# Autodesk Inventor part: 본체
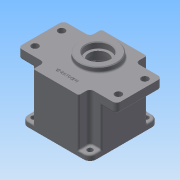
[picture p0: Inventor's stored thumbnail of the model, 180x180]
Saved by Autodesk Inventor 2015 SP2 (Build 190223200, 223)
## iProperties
Created: 2015-06
Part Number: 본체
Material: 일반
Document SubType Name: Modeling
Designer: AMC
Density: 1 g/cm^3
Appearance: 기본값
Author: AMC
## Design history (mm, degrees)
sketch "스케치1"
  geometry: L1 (65, 30)-(65, -30); L2 (-65, -30)-(-65, 30); L3 (30, -45)-(-30, -45); L4 (-30, 45)-(30, 45); L5 (-65, 30)-(-30, 30); L6 (30, 30)-(65, 30); L7 (65, -30)-(30, -30); L8 (-30, -30)-(-65, -30); L9 (30, 45)-(30, 30); L10 (30, -30)-(30, -45); L11 (-30, -45)-(-30, -30); L12 (-30, 30)-(-30, 45); 3 further points
  constraints: 24 end point, 10 parallel, 4 perpendicular, 3 horizontal, 3 horizontal alignment, 3 vertical alignment, 2 collinear, 2 midpoint
  dimensions: "d0" = 60 distance of L4.start L4.end; "d1" = 60 distance of L1.start L1.end; "d2" = 130 distance between parallel lines of L1 L2; "d3" = 90 distance between parallel lines of L3 L4
extrude "돌출1" new body sketch "스케치1" distance "d4" = 12; taper "d5" = 0 deg
sketch "스케치2"
  geometry: L1 (-45, 45)-(45, 45); L2 (45, 45)-(45, -45); L3 (45, -45)-(-45, -45); L4 (-45, -45)-(-45, 45); L5 (-30, 45)-(30, 45) reference; 2 further points
  constraints: 8 end point, 2 midpoint, 2 parallel, 2 perpendicular, 1 horizontal
  dimensions: "d6" = 90 distance of L1.start L1.end
extrude "돌출2" join sketch "스케치2" distance "d7" = 58; taper "d8" = 0 deg
sketch "스케치3"
  geometry: L1 (45, 45)-(30, 45); L2 (30, 45)-(30, 30); L3 (30, 30)-(45, 30); L4 (45, 30)-(45, 45); 1 further point
  constraints: 8 end point, 2 parallel, 1 horizontal, 1 perpendicular
extrude "돌출3" cut sketch "스케치3" distance "d9" = 51; taper "d10" = 0 deg
fillet "모깎기1" dims "d11" = 8
hole "구멍1" diameter "d14" = 7; stored, may be unused: countersink angle "d18" = 90 deg, drill point angle "d20" = 118 deg; dims "d12" = 10, "d13" = 10, "d15" = 6, "d16" = 4, "d17" = 2, "d19" = 8
fillet "모깎기2" dims "d21" = 5
fillet "모깎기3" dims "d22" = 5
fillet "모깎기4" dims "d23" = 8
fillet "모깎기5" dims "d24" = 2
fillet "모깎기6" dims "d25" = 2
fillet "모깎기7" dims "d26" = 5
sketch "스케치4"
  geometry: 3 further points
  constraints: 1 vertical alignment
  dimensions: "d27" = 35 distance of point (-55, -17.5) point (-55, 17.5); "d28" = 17.5 vertical distance of point (0, 0) point (-55, 17.5); "d29" = 55 horizontal distance of point (0, 0) point (-55, 17.5)
hole "구멍2" sketch "스케치4" at (-55, 17.5), (-55, -17.5) diameter "d30" = 9; stored, may be unused: countersink angle "d34" = 90 deg, drill point angle "d36" = 118 deg; dims "d31" = 6, "d32" = 4, "d33" = 2, "d35" = 8
fillet "모깎기8" dims "d37" = 2
sketch "스케치5"
  geometry: C1 r 25 at (0, 11); 1 further point
  constraints: 1 centre point, 1 vertical alignment
  dimensions: "d38" = 50 diameter of C1; "d39" = 11 distance of point (0, 0) C1.centre
extrude "돌출4" join sketch "스케치5" distance "d40" = 7; taper "d41" = 0 deg
sketch "스케치6"
  geometry: 1 further point
hole "구멍3" sketch "스케치6" at (0, 0) diameter "d42" = 78; stored, may be unused: countersink angle "d46" = 90 deg, drill point angle "d48" = 0 deg; dims "d43" = 6, "d44" = 80, "d45" = 9, "d47" = 61
sketch "스케치7"
  geometry: L1 (0, 0)-(30.77, 30.77); L2 (0, 0)-(43.515, 0); L3 (24.603, 30.26)-(21.758, 27.415); L4 (30.26, 24.603)-(27.415, 21.758); A1 r 35 centre (0, 0) between (24.749, 24.749) and (27.415, 21.758); A2 r 4 centre (24.749, 24.749) between (21.92, 27.577) and (27.577, 21.92); A3 r 39 centre (0, 0) between (30.26, 24.603) and (24.603, 30.26); 1 further point
  constraints: 8 end point, 7 point on circle, 3 centre point, 3 point on line, 2 coincident, 2 tangent, 1 equal length, 1 horizontal
  dimensions: "d49" = 70 diameter of A1; "d50" = 45 deg angle of L2 L1; "d52" = 78 diameter of A3; "d53" = 8 diameter of A2
extrude "돌출5" join sketch "스케치7" stored distance "d55" = 7; taper "d56" = 0 deg
fillet "모깎기9" dims "d57" = 3.5
fillet "모깎기10" dims "d61" = 2
hole "구멍4" diameter "d64" = 3.459; stored, may be unused: countersink angle "d68" = 90 deg, drill point angle "d70" = 118 deg; dims "d65" = 12, "d66" = 80, "d67" = 9, "d69" = 15, "d155" = 10, "d156" = 10
sketch "스케치10"
  geometry: A1 r 20.5 centre (0, 11) between (7.402, -8.117) and (-7.402, -8.117); A2 r 14 centre (0, -20) between (-7.402, -8.117) and (7.402, -8.117); 1 further point
  constraints: 4 point on circle, 2 centre point, 2 vertical alignment
  dimensions: "d105" = 41 diameter of A1; "d106" = 11 distance of point (0, 0) A1.centre; "d107" = 28 diameter of A2; "d108" = 20 distance of point (0, 0) A2.centre
extrude "돌출8" join sketch "스케치10" distance "d109" = 7; taper "d110" = 0 deg
fillet "모깎기13" dims "d111" = 3
fillet "모깎기14" dims "d112" = 2
hole "구멍7" diameter "d115" = 35; stored, may be unused: countersink angle "d119" = 90 deg, drill point angle "d121" = 0 deg; dims "d113" = 10, "d114" = 10, "d116" = 6, "d117" = 32, "d118" = 8, "d120" = 10
hole "구멍8" diameter "d124" = 25; stored, may be unused: countersink angle "d128" = 90 deg, drill point angle "d130" = 0 deg; dims "d122" = 10, "d123" = 10, "d125" = 6, "d126" = 32, "d127" = 8, "d129" = 10
fillet "모깎기15" dims "d131" = 0.3
fillet "모깎기16" dims "d132" = 2
chamfer "모따기2" distance "d133" = 1; stored, may be unused: second distance "d134" = 2, angle "d135" = 45 deg
hole "구멍9" diameter "d138" = 19; stored, may be unused: countersink angle "d142" = 90 deg, drill point angle "d144" = 0 deg; dims "d136" = 10, "d137" = 10, "d139" = 6, "d140" = 22, "d141" = 7, "d143" = 8
fillet "모깎기17" dims "d145" = 2
fillet "모깎기18" dims "d146" = 0.3
chamfer "모따기3" distance "d147" = 1; stored, may be unused: second distance "d148" = 2, angle "d149" = 45 deg
sketch "스케치11"
  geometry: L1 (-28, -45)-(28, -45) reference; 3 further points
  constraints: 1 midpoint, 1 vertical alignment, 1 other
  dimensions: "d150" = 15 distance of point (0, -45) point (0, -30)
extrude "돌출9" join sketch "스케치11" distance "d151" = 0.5; taper "d152" = 0 deg
node "솔리드1"
mirror "대칭1"
mirror "대칭2"
mirror "대칭3"
pattern_circular "원형 패턴1" dims angle "d59" = 360 deg
pattern_circular "원형 패턴2" dims angle "d72" = 360 deg
